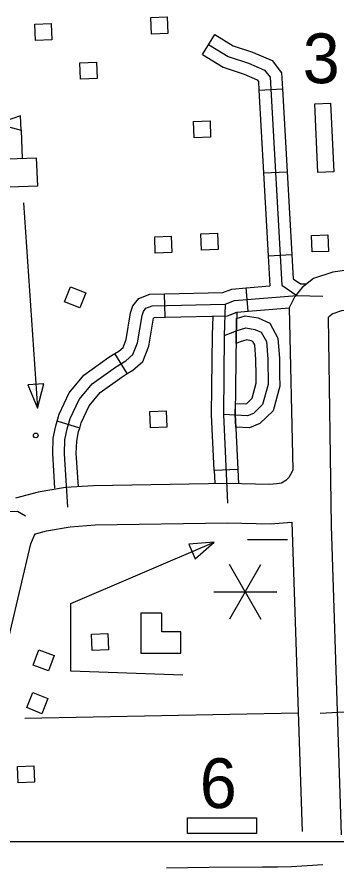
# Model space of a CAD drawing. Extents: x 1671357 to 13005564, y 567358 to 14261451.
# Drawn here: x 12758275.41 to 12758279.26, y 14259853.64 to 14259863.9 of the extents above; entities that cross this region are included whole.
import ezdxf

# ---------------------------------------------------------------- set-up
doc = ezdxf.new("R2010")
doc.units = 0
for name, color, linetype in [('10', 7, 'Continuous'), ('2', 7, 'Continuous'), ('31', 7, 'Continuous'), ('32', 7, 'Continuous'), ('48', 7, 'Continuous'), ('5', 7, 'Continuous'), ('56', 7, 'Continuous')]:
    doc.layers.add(name, color=color, linetype=linetype)

msp = doc.modelspace()

# ---------------------------------------------------------------- linework, layer by layer
at = {"layer": '10'}
for points in [[(12758279.499, 14259860.864), (12758279.212, 14259860.825), (12758278.978, 14259860.747), (12758278.842, 14259860.642), (12758278.752, 14259860.532), (12758278.685, 14259860.396), (12758278.728, 14259858.443), (12758278.721, 14259858.423), (12758278.681, 14259858.352), (12758278.644, 14259858.315), (12758278.592, 14259858.284), (12758278.535, 14259858.273), (12758278.448, 14259858.265), (12758277.944, 14259858.279), (12758276.327, 14259858.252), (12758275.989, 14259858.229), (12758275.66, 14259858.172), (12758275.387, 14259858.1)], [(12758279.317, 14259854.045), (12758279.194, 14259857.769), (12758279.161, 14259860.283), (12758279.175, 14259860.3), (12758279.205, 14259860.323), (12758279.319, 14259860.362), (12758279.545, 14259860.392), (12758280.582, 14259860.457), (12758281.163, 14259860.501)], [(12758275.572, 14259857.551), (12758275.612, 14259857.648), (12758275.627, 14259857.673), (12758275.762, 14259857.709), (12758276.046, 14259857.758), (12758276.347, 14259857.779), (12758277.942, 14259857.805), (12758278.462, 14259857.791), (12758278.719, 14259857.814), (12758278.842, 14259854.083)], [(12758263.324, 14259854.033), (12758263.343, 14259854.05), (12758263.463, 14259854.196), (12758263.655, 14259854.637), (12758263.68, 14259854.679), (12758263.808, 14259854.82), (12758263.973, 14259854.945), (12758264.036, 14259854.975), (12758264.063, 14259854.983), (12758268.719, 14259855.072), (12758274.49, 14259855.167), (12758274.715, 14259855.191), (12758274.93, 14259855.304), (12758275.071, 14259855.431), (12758275.572, 14259857.551)]]:
    msp.add_lwpolyline(points, dxfattribs=at)
at = {"layer": '2'}
msp.add_line((12758241.074, 14259853.963), (12758347.684, 14259853.963), dxfattribs=at)
at = {"layer": '31'}
msp.add_line((12758278.066, 14259858.447), (12758277.782, 14259858.434), dxfattribs=at)
for points in [[(12758277.915, 14259860.44), (12758277.904, 14259860.063), (12758277.893, 14259859.109), (12758277.943, 14259858.042)], [(12758277.769, 14259860.294), (12758277.944, 14259860.299), (12758278.054, 14259860.341)], [(12758278.054, 14259860.341), (12758278.046, 14259860.06)], [(12758277.755, 14259859.442), (12758277.762, 14259860.066), (12758277.769, 14259860.294)], [(12758278.045, 14259859.964), (12758278.052, 14259860.268)], [(12758278.052, 14259860.268), (12758278.154, 14259860.299), (12758278.313, 14259860.274), (12758278.452, 14259860.209), (12758278.55, 14259860.031), (12758278.569, 14259859.784), (12758278.571, 14259859.588)], [(12758277.904, 14259860.063), (12758278.011, 14259860.103), (12758278.048, 14259860.118), (12758278.164, 14259860.153), (12758278.271, 14259860.136), (12758278.35, 14259860.1), (12758278.411, 14259859.99), (12758278.427, 14259859.778), (12758278.431, 14259859.47), (12758278.366, 14259859.23), (12758278.255, 14259859.123), (12758278.182, 14259859.093), (12758277.893, 14259859.109)], [(12758278.046, 14259860.06), (12758278.039, 14259859.438)], [(12758278.287, 14259859.585), (12758278.285, 14259859.771), (12758278.272, 14259859.948), (12758278.248, 14259859.99), (12758278.229, 14259859.999), (12758278.174, 14259860.008), (12758278.095, 14259859.984), (12758278.045, 14259859.964)], [(12758278.037, 14259859.243), (12758278.158, 14259859.237), (12758278.176, 14259859.244), (12758278.239, 14259859.305), (12758278.289, 14259859.488), (12758278.287, 14259859.585)], [(12758278.571, 14259859.588), (12758278.573, 14259859.452), (12758278.493, 14259859.154), (12758278.333, 14259859.001), (12758278.206, 14259858.95), (12758278.042, 14259858.958)], [(12758277.782, 14259858.434), (12758277.751, 14259859.106), (12758277.755, 14259859.442)], [(12758278.039, 14259859.438), (12758278.035, 14259859.111)], [(12758278.042, 14259858.958), (12758278.036, 14259859.109), (12758278.037, 14259859.243)], [(12758278.035, 14259859.111), (12758278.066, 14259858.447)], [(12758277.782, 14259858.434), (12758277.79, 14259858.283)], [(12758278.066, 14259858.447), (12758278.074, 14259858.275)]]:
    msp.add_lwpolyline(points, dxfattribs=at)
at = {"layer": '32'}
for p, q in [((12758277.641, 14259863.446), (12758277.788, 14259863.688)), ((12758278.322, 14259863.019), (12758278.605, 14259863.035)), ((12758278.378, 14259862.02), (12758278.661, 14259862.036)), ((12758278.434, 14259861.022), (12758278.717, 14259861.038)), ((12758278.191, 14259860.353), (12758278.168, 14259860.637)), ((12758277.192, 14259860.281), (12758277.185, 14259860.565)), ((12758276.734, 14259859.602), (12758276.584, 14259859.844)), ((12758276.161, 14259858.947), (12758275.889, 14259859.029))]:
    msp.add_line(p, q, dxfattribs=at)
for points in [[(12758277.788, 14259863.688), (12758278.009, 14259863.554), (12758278.245, 14259863.475), (12758278.479, 14259863.375), (12758278.594, 14259863.228), (12758278.605, 14259863.035)], [(12758277.715, 14259863.567), (12758277.949, 14259863.424), (12758278.195, 14259863.342), (12758278.389, 14259863.259), (12758278.455, 14259863.176), (12758278.596, 14259860.668), (12758278.779, 14259860.544)], [(12758277.641, 14259863.446), (12758277.889, 14259863.294), (12758278.144, 14259863.209), (12758278.3, 14259863.142), (12758278.316, 14259863.123), (12758278.322, 14259863.019)], [(12758278.322, 14259863.019), (12758278.378, 14259862.02)], [(12758278.605, 14259863.035), (12758278.661, 14259862.036)], [(12758278.378, 14259862.02), (12758278.434, 14259861.022)], [(12758278.661, 14259862.036), (12758278.717, 14259861.038)], [(12758278.717, 14259861.038), (12758278.734, 14259860.746), (12758278.824, 14259860.685)], [(12758278.434, 14259861.022), (12758278.454, 14259860.66)], [(12758277.185, 14259860.565), (12758277.887, 14259860.581), (12758277.993, 14259860.622), (12758278.168, 14259860.637)], [(12758278.168, 14259860.637), (12758278.453, 14259860.66)], [(12758278.824, 14259860.685), (12758278.895, 14259860.683)], [(12758276.018, 14259857.994), (12758275.978, 14259858.64), (12758275.983, 14259858.806), (12758276.01, 14259858.938), (12758276.047, 14259859.061), (12758276.156, 14259859.292), (12758276.31, 14259859.478), (12758276.592, 14259859.681), (12758276.716, 14259859.758), (12758276.803, 14259859.834), (12758276.858, 14259859.973), (12758276.914, 14259860.302), (12758276.929, 14259860.352), (12758276.96, 14259860.39), (12758277.036, 14259860.419), (12758277.915, 14259860.44), (12758278.025, 14259860.482), (12758278.779, 14259860.544), (12758279.092, 14259860.535)], [(12758276.584, 14259859.844), (12758276.632, 14259859.873), (12758276.683, 14259859.918), (12758276.72, 14259860.012), (12758276.775, 14259860.335), (12758276.801, 14259860.421), (12758276.874, 14259860.509), (12758277.008, 14259860.561), (12758277.185, 14259860.565)], [(12758277.192, 14259860.281), (12758277.943, 14259860.299), (12758278.057, 14259860.342), (12758278.191, 14259860.353)], [(12758278.191, 14259860.353), (12758278.684, 14259860.394)], [(12758276.734, 14259859.602), (12758276.801, 14259859.644), (12758276.922, 14259859.75), (12758276.996, 14259859.935), (12758277.052, 14259860.27), (12758277.053, 14259860.273), (12758277.064, 14259860.278), (12758277.192, 14259860.281)], [(12758275.889, 14259859.029), (12758275.914, 14259859.112), (12758276.035, 14259859.369), (12758276.212, 14259859.583), (12758276.513, 14259859.8), (12758276.584, 14259859.844)], [(12758276.161, 14259858.947), (12758276.18, 14259859.01), (12758276.277, 14259859.215), (12758276.408, 14259859.374), (12758276.671, 14259859.563), (12758276.734, 14259859.602)], [(12758275.862, 14259858.22), (12758275.836, 14259858.638), (12758275.842, 14259858.823), (12758275.873, 14259858.973), (12758275.889, 14259859.029)], [(12758276.145, 14259858.24), (12758276.12, 14259858.643), (12758276.125, 14259858.789), (12758276.148, 14259858.903), (12758276.161, 14259858.947)], [(12758275.506, 14259857.886), (12758275.413, 14259857.94), (12758274.029, 14259857.922), (12758272.919, 14259857.915), (12758271.974, 14259857.886), (12758270.365, 14259857.846), (12758270.132, 14259857.843), (12758269.867, 14259857.844), (12758269.688, 14259857.865), (12758269.498, 14259857.877), (12758269.296, 14259857.871), (12758268.998, 14259857.863), (12758268.671, 14259857.858)], [(12758281.299, 14259855.63), (12758279.059, 14259855.507)], [(12758277.208, 14259853.645), (12758277.721, 14259853.654), (12758278.365, 14259853.658), (12758278.545, 14259853.659), (12758278.712, 14259853.662), (12758279.092, 14259853.686)]]:
    msp.add_lwpolyline(points, dxfattribs=at)
at = {"layer": '48'}
for p, q in [((12758278.157, 14259856.973), (12758277.968, 14259857.301)), ((12758278.157, 14259856.973), (12758278.346, 14259857.301)), ((12758277.778, 14259856.973), (12758278.157, 14259856.973)), ((12758278.157, 14259856.973), (12758277.968, 14259856.645)), ((12758278.157, 14259856.973), (12758278.536, 14259856.973)), ((12758278.157, 14259856.973), (12758278.346, 14259856.645))]:
    msp.add_line(p, q, dxfattribs=at)
at = {"layer": '5'}
msp.add_lwpolyline([(12758278.795, 14259855.51), (12758275.498, 14259855.446)], dxfattribs=at)
at = {"layer": '56'}
msp.add_line((12758275.454, 14259862.537), (12758275.467, 14259862.196), dxfattribs=at)
for points in [[(12758275.628, 14259863.618), (12758275.62, 14259863.815), (12758275.818, 14259863.823), (12758275.826, 14259863.626)], [(12758277.025, 14259863.695), (12758277.017, 14259863.892), (12758277.215, 14259863.9), (12758277.222, 14259863.703)], [(12758276.172, 14259863.15), (12758276.164, 14259863.347), (12758276.362, 14259863.355), (12758276.37, 14259863.158)], [(12758278.993, 14259862.852), (12758279.182, 14259862.861), (12758279.222, 14259862.033), (12758279.032, 14259862.024)], [(12758275.448, 14259862.707), (12758275.167, 14259862.611), (12758275.454, 14259862.537)], [(12758277.542, 14259862.444), (12758277.534, 14259862.641), (12758277.732, 14259862.648), (12758277.739, 14259862.451)], [(12758275.31, 14259861.848), (12758275.297, 14259862.189), (12758275.638, 14259862.202), (12758275.651, 14259861.862)], [(12758277.072, 14259861.053), (12758277.065, 14259861.25), (12758277.262, 14259861.257), (12758277.27, 14259861.06)], [(12758277.63, 14259861.09), (12758277.623, 14259861.287), (12758277.82, 14259861.294), (12758277.828, 14259861.097)], [(12758278.962, 14259861.068), (12758278.954, 14259861.265), (12758279.152, 14259861.273), (12758279.159, 14259861.076)], [(12758275.978, 14259860.467), (12758276.051, 14259860.65), (12758276.234, 14259860.577), (12758276.161, 14259860.394)], [(12758275.73, 14259859.481), (12758275.537, 14259859.468), (12758275.653, 14259859.185)], [(12758277.015, 14259858.95), (12758277.008, 14259859.147), (12758277.205, 14259859.155), (12758277.213, 14259858.958)], [(12758277.478, 14259857.549), (12758277.551, 14259857.371), (12758277.782, 14259857.57)], [(12758276.898, 14259856.235), (12758277.38, 14259856.235), (12758277.38, 14259856.489), (12758277.152, 14259856.489), (12758277.152, 14259856.717), (12758276.898, 14259856.717)], [(12758276.312, 14259856.264), (12758276.304, 14259856.461), (12758276.502, 14259856.469), (12758276.51, 14259856.272)], [(12758275.601, 14259856.088), (12758275.668, 14259856.274), (12758275.854, 14259856.207), (12758275.787, 14259856.021)], [(12758275.522, 14259855.577), (12758275.595, 14259855.76), (12758275.779, 14259855.686), (12758275.705, 14259855.503)], [(12758275.42, 14259854.672), (12758275.412, 14259854.869), (12758275.61, 14259854.877), (12758275.617, 14259854.68)], [(12758277.462, 14259854.061), (12758277.462, 14259854.25), (12758278.29, 14259854.25), (12758278.29, 14259854.061)]]:
    msp.add_lwpolyline(points, close=True, dxfattribs=at)
for points in [[(12758275.485, 14259861.659), (12758275.653, 14259859.185)], [(12758277.403, 14259855.968), (12758276.054, 14259856.017), (12758276.054, 14259856.834), (12758277.782, 14259857.57)], [(12758278.184, 14259857.605), (12758278.666, 14259857.605)]]:
    msp.add_lwpolyline(points, dxfattribs=at)
msp.add_circle((12758275.632, 14259858.858), 0.0284, dxfattribs=at)

# ---------------------------------------------------------------- texts
for s, p in [('3', (12758278.849, 14259863.102)), ('6', (12758277.608, 14259854.367))]:
    msp.add_text(s, height=0.6, dxfattribs=at).set_placement(p)

doc.saveas('drawing.dxf')
